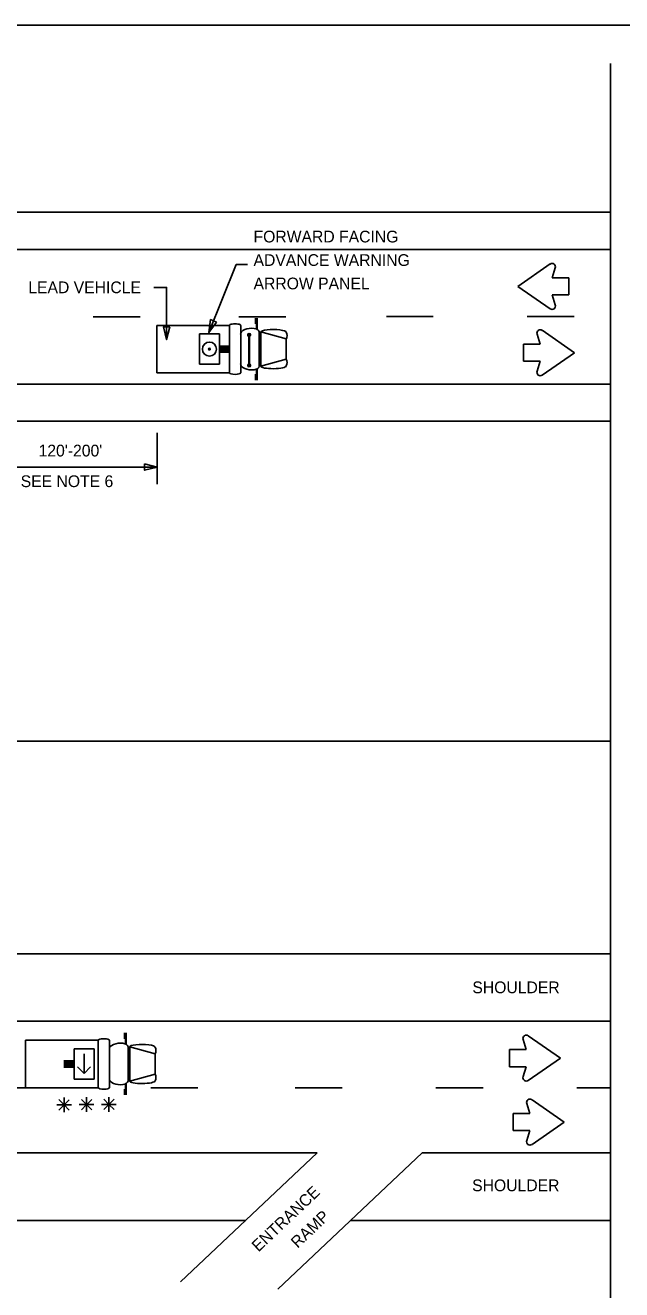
# Model space of a CAD drawing. Extents: x 1416408 to 1429341, y 372694 to 383211.
# Drawn here: x 1427162 to 1427672, y 373399 to 374480 of the extents above; entities that cross this region are included whole.
import ezdxf

# ---------------------------------------------------------------- set-up
doc = ezdxf.new("R2010")
doc.units = 0
for name, color, linetype in [('Default', 7, 'Continuous'), ('DSN_DRFT_Junk-No-Plot', 7, 'Continuous'), ('Working Level 1', 7, 'Continuous')]:
    doc.layers.add(name, color=color, linetype=linetype)

msp = doc.modelspace()

# ---------------------------------------------------------------- linework, layer by layer
at = {"layer": 'Default'}
for points in [[(1426234.9, 374479.9), (1426234.9, 372693.9), (1428995.1, 372693.9), (1428995.1, 374479.9)], [(1426234.9, 374479.9), (1426234.9, 372693.9), (1428995.1, 372693.9), (1428995.1, 374479.9)], [(1426234.9, 374479.9), (1428995.1, 374479.9), (1428995.1, 372693.9), (1426234.9, 372693.9)], [(1426234.9, 374479.9), (1426234.9, 372693.9), (1428995.1, 372693.9), (1428995.1, 374479.9)]]:
    msp.add_lwpolyline(points, close=True, dxfattribs=at)
at = {"layer": 'DSN_DRFT_Junk-No-Plot'}
msp.add_lwpolyline([(1426234.9, 374479.9), (1428995.1, 374479.9), (1428995.1, 372693.9), (1426234.9, 372693.9)], close=True, dxfattribs=at)
at = {"layer": 'Working Level 1'}
for p, q in [((1427662.6, 374447.3), (1427662.6, 372727.2)), ((1426338, 374320.2), (1427662.5, 374320.2)), ((1426338, 374288.1), (1427662.5, 374288.1)), ((1427583.2, 374256.6), (1427610.8, 374275.8)), ((1427612.6, 374263.9), (1427615.3, 374272.4)), ((1427583.2, 374256.6), (1427610.8, 374237.5)), ((1427626.9, 374263.9), (1427612.6, 374263.9)), ((1427626.9, 374263.9), (1427626.9, 374249.3)), ((1427626.9, 374249.3), (1427612.6, 374249.3)), ((1427612.6, 374249.3), (1427615.3, 374240.8)), ((1427359.1, 374224.6), (1427359.1, 374229.5)), ((1427359.9, 374219.8), (1427359.9, 374229.5)), ((1427360.5, 374219.8), (1427360.5, 374229.5)), ((1427274.5, 374223.3), (1427336.7, 374223.3)), ((1427274.5, 374182.7), (1427274.5, 374223.3)), ((1427274.5, 374223.3), (1427274.5, 374182.7)), ((1427311.1, 374216), (1427328.1, 374216)), ((1427311.1, 374216), (1427311.1, 374190)), ((1427328.1, 374190), (1427328.1, 374216)), ((1427336.7, 374203), (1427336.7, 374223.3)), ((1427346.3, 374203), (1427346.3, 374223.3)), ((1427352.3, 374215.4), (1427352.3, 374215.4)), ((1427353.4, 374214.8), (1427353.4, 374189.6)), ((1427353.4, 374214.8), (1427353.4, 374189.6)), ((1427353.5, 374214.8), (1427353.5, 374189.6)), ((1427353.6, 374214.8), (1427353.6, 374189.6)), ((1427353.8, 374216.2), (1427353.8, 374216.2)), ((1427353.8, 374214.8), (1427353.8, 374189.6)), ((1427362.2, 374203), (1427362.2, 374217.7)), ((1427363.5, 374217.7), (1427385.3, 374211.7)), ((1427363.5, 374203), (1427363.5, 374217.7)), ((1427602.4, 374207.2), (1427599.7, 374215.7)), ((1427631.7, 374199.9), (1427604.1, 374219.1)), ((1427328.1, 374205.6), (1427336.7, 374205.6)), ((1427328.1, 374204.3), (1427336.7, 374204.3)), ((1427328.1, 374203), (1427336.7, 374203)), ((1427336.7, 374203), (1427336.7, 374182.7)), ((1427346.3, 374203), (1427346.3, 374182.7)), ((1427362.2, 374203), (1427362.2, 374188.4)), ((1427363.5, 374203), (1427363.5, 374188.4)), ((1427385.3, 374203), (1427385.3, 374211.7)), ((1427385.3, 374203), (1427385.3, 374194.4)), ((1427588, 374192.6), (1427588, 374207.2)), ((1427588, 374207.2), (1427602.4, 374207.2)), ((1427328.1, 374201.7), (1427336.7, 374201.7)), ((1427328.1, 374200.4), (1427336.7, 374200.4)), ((1427363.5, 374188.4), (1427385.3, 374194.4)), ((1427588, 374192.6), (1427602.4, 374192.6)), ((1427602.4, 374192.6), (1427599.7, 374184.1)), ((1427631.7, 374199.9), (1427604.1, 374180.8)), ((1427274.5, 374182.7), (1427336.7, 374182.7)), ((1427311.1, 374190), (1427328.1, 374190)), ((1427352.4, 374189.4), (1427352.4, 374189.4)), ((1427353.9, 374190.2), (1427353.9, 374190.2)), ((1427359.1, 374181.5), (1427359.1, 374176.5)), ((1427359.9, 374186.3), (1427359.9, 374176.5)), ((1427360.5, 374186.3), (1427360.5, 374176.5)), ((1426338, 374173.1), (1427662.5, 374173.1)), ((1426338, 374141.5), (1427662.5, 374141.5)), ((1427274.8, 374131.4), (1427274.8, 374087.5)), ((1427136.9, 374102.1), (1427274.8, 374102.1)), ((1426338, 373867.7), (1427663, 373867.7)), ((1426338, 373686), (1427663, 373686)), ((1426819.9, 373628.3), (1427663, 373628.3)), ((1427246.9, 373613.2), (1427246.9, 373618.2)), ((1427247.7, 373608.5), (1427247.7, 373618.2)), ((1427248.3, 373608.5), (1427248.3, 373618.2)), ((1427162.4, 373612), (1427224.5, 373612)), ((1427162.4, 373571.4), (1427162.4, 373612)), ((1427162.4, 373612), (1427162.4, 373571.4)), ((1427224.5, 373591.7), (1427224.5, 373612)), ((1427234.1, 373591.7), (1427234.1, 373612)), ((1427590.5, 373604), (1427587.8, 373612.5)), ((1427619.8, 373596.7), (1427592.2, 373615.9)), ((1427220.9, 373604.7), (1427203.9, 373604.7)), ((1427203.9, 373578.7), (1427203.9, 373604.7)), ((1427212.4, 373600.3), (1427212.4, 373583.7)), ((1427220.9, 373604.7), (1427220.9, 373578.7)), ((1427250, 373591.7), (1427250, 373606.4)), ((1427251.4, 373606.4), (1427273.1, 373600.3)), ((1427251.4, 373591.7), (1427251.4, 373606.4)), ((1427273.1, 373591.7), (1427273.1, 373600.3)), ((1427576.1, 373589.4), (1427576.1, 373604)), ((1427576.1, 373604), (1427590.5, 373604)), ((1427619.8, 373596.7), (1427592.2, 373577.6)), ((1427203.9, 373594.3), (1427195.2, 373594.3)), ((1427203.9, 373593), (1427195.2, 373593)), ((1427203.9, 373591.7), (1427195.2, 373591.7)), ((1427203.9, 373590.4), (1427195.2, 373590.4)), ((1427203.9, 373589.1), (1427195.2, 373589.1)), ((1427212.4, 373583.7), (1427206.8, 373589.3)), ((1427212.4, 373583.7), (1427217.8, 373589.2)), ((1427224.5, 373591.7), (1427224.5, 373571.4)), ((1427234.1, 373591.7), (1427234.1, 373571.4)), ((1427250, 373591.7), (1427250, 373577.1)), ((1427251.4, 373591.7), (1427251.4, 373577.1)), ((1427273.1, 373591.7), (1427273.1, 373583.1)), ((1427576.1, 373589.4), (1427590.5, 373589.4)), ((1427590.5, 373589.4), (1427587.8, 373580.9)), ((1427220.9, 373578.7), (1427203.9, 373578.7)), ((1427247.7, 373575), (1427247.7, 373565.2)), ((1427248.3, 373575), (1427248.3, 373565.2)), ((1427251.4, 373577.1), (1427273.1, 373583.1)), ((1427162.4, 373571.4), (1427224.5, 373571.4)), ((1427246.9, 373570.2), (1427246.9, 373565.2)), ((1427633.8, 373571.4), (1427663, 373571.4)), ((1427195.3, 373556.7), (1427189.1, 373556.7)), ((1427195.3, 373556.7), (1427190.9, 373561.2)), ((1427195.3, 373556.7), (1427190.9, 373552.3)), ((1427195.2, 373556.6), (1427199.6, 373561.1)), ((1427195.3, 373556.7), (1427195.3, 373563)), ((1427195.3, 373556.7), (1427199.7, 373552.3)), ((1427195.3, 373556.7), (1427195.3, 373550.4)), ((1427195.3, 373556.7), (1427201.6, 373556.7)), ((1427214.6, 373557), (1427208.3, 373557)), ((1427214.6, 373557), (1427210.2, 373561.4)), ((1427214.6, 373557), (1427210.2, 373552.5)), ((1427214.5, 373556.9), (1427218.9, 373561.3)), ((1427214.6, 373557), (1427214.6, 373563.3)), ((1427214.6, 373557), (1427219, 373552.5)), ((1427214.6, 373557), (1427214.6, 373550.7)), ((1427214.6, 373557), (1427220.8, 373557)), ((1427233.7, 373557.1), (1427227.4, 373557.1)), ((1427233.7, 373557.1), (1427229.3, 373561.6)), ((1427233.7, 373557.1), (1427229.3, 373552.7)), ((1427233.6, 373557), (1427238, 373561.5)), ((1427233.7, 373557.1), (1427233.7, 373563.4)), ((1427233.7, 373557.1), (1427238.1, 373552.7)), ((1427233.7, 373557.1), (1427233.7, 373550.8)), ((1427233.7, 373557.1), (1427239.9, 373557.1)), ((1427593.6, 373549.3), (1427590.9, 373557.8)), ((1427623, 373542), (1427595.4, 373561.1)), ((1427579.3, 373534.7), (1427579.3, 373549.3)), ((1427579.3, 373549.3), (1427593.6, 373549.3)), ((1427579.3, 373534.7), (1427593.6, 373534.7)), ((1427593.6, 373534.7), (1427590.9, 373526.2)), ((1427623, 373542), (1427595.4, 373522.9)), ((1426338, 373515.7), (1427411.7, 373515.7)), ((1427411.7, 373515.7), (1427294.9, 373405.3)), ((1427501.4, 373515.7), (1427378, 373399.1)), ((1427501.4, 373515.7), (1427663, 373515.7)), ((1426338, 373458), (1427350.7, 373458)), ((1427440.3, 373458), (1427663, 373458))]:
    msp.add_line(p, q, dxfattribs=at)
for points in [[(1427319.1, 374217.1), (1427342.5, 374275.3), (1427352.1, 374275.3)], [(1427283, 374211.1), (1427283, 374255.8), (1427272, 374255.8)], [(1427220.3, 374230.5), (1427260.5, 374230.5)], [(1427344.7, 374230.5), (1427384.9, 374230.5)], [(1427470.9, 374231), (1427511, 374231)], [(1427591.4, 374231), (1427631.5, 374231)], [(1427352.3, 374215.4), (1427353.1, 374214)], [(1427352.3, 374214.9), (1427352.7, 374214.2)], [(1427352.4, 374215.7), (1427353.4, 374213.9)], [(1427352.6, 374215.9), (1427353.7, 374213.9)], [(1427352.8, 374216.1), (1427354, 374214)], [(1427353, 374216.2), (1427354.2, 374214.1)], [(1427353.2, 374216.3), (1427354.3, 374214.3)], [(1427353.4, 374216.3), (1427354.5, 374214.5)], [(1427353.8, 374216.3), (1427354.6, 374214.8)], [(1427354.1, 374216.2), (1427354.7, 374215.2)], [(1427352.4, 374189.4), (1427353.2, 374188)], [(1427352.4, 374188.9), (1427352.8, 374188.2)], [(1427352.5, 374189.7), (1427353.5, 374187.9)], [(1427352.7, 374189.9), (1427353.8, 374187.9)], [(1427352.8, 374190.1), (1427354, 374188)], [(1427353, 374190.2), (1427354.2, 374188.1)], [(1427353.3, 374190.3), (1427354.4, 374188.3)], [(1427353.5, 374190.3), (1427354.6, 374188.5)], [(1427353.8, 374190.3), (1427354.7, 374188.8)], [(1427354.2, 374190.2), (1427354.8, 374189.1)], [(1427146.8, 373571.4), (1427187, 373571.4)], [(1427269.5, 373571.4), (1427309.7, 373571.4)], [(1427392.8, 373571.4), (1427433, 373571.4)], [(1427513.3, 373571.4), (1427553.5, 373571.4)]]:
    msp.add_lwpolyline(points, dxfattribs=at)
for points in [[(1427325.6, 374226.1), (1427319.1, 374217.1), (1427320.6, 374228.2)], [(1427285.6, 374222), (1427283, 374211.1), (1427280.3, 374222)], [(1427264.1, 374104.8), (1427274.8, 374102.1), (1427264.1, 374099.4)]]:
    msp.add_lwpolyline(points, close=True, dxfattribs=at)
for centre, major_axis, ratio, start_param, end_param in [((1427612.5, 374273.3), (0, -2.96), 0.989089, 1.259821, 3.74278), ((1427612.5, 374239.9), (0, -2.96), 0.989089, 5.681999, 8.164958), ((1427341.5, 374223.3), (4.76, 0), 0.27289, 6.283185, 9.424778), ((1427354.2, 374216.7), (7.98, 1.01), 0.50847, 6.28135, 9.422943), ((1427374.4, 374217.5), (10.9, -0.1), 0.205643, 0.000054, 3.141647), ((1427380, 374214.5), (0, 6.1), 0.989089, 4.221603, 5.203174), ((1427602.5, 374216.6), (0, 2.96), 0.989089, 5.681999, 8.164958), ((1427380, 374191.5), (0, 6.1), 0.989089, 4.221604, 5.203174), ((1427341.5, 374182.7), (4.76, 0), 0.27289, 3.141593, 6.283185), ((1427354.2, 374189.4), (7.98, -1.01), 0.50847, 3.143427, 6.28502), ((1427374.4, 374188.5), (10.9, 0.1), 0.205643, 3.141539, 6.283131), ((1427602.5, 374183.2), (0, 2.96), 0.989089, 1.259821, 3.74278), ((1427229.3, 373612), (4.76, 0), 0.27289, 6.283185, 9.424778), ((1427242, 373605.4), (7.98, 1.01), 0.50847, 6.28135, 9.422943), ((1427262.2, 373606.2), (10.9, -0.1), 0.205643, 0.000054, 3.141647), ((1427590.6, 373613.4), (0, 2.96), 0.989089, 5.681999, 8.164958), ((1427267.8, 373603.2), (0, 6.1), 0.989089, 4.221603, 5.203174), ((1427242, 373578.1), (7.98, -1.01), 0.50847, 3.143427, 6.28502), ((1427262.2, 373577.2), (10.9, 0.1), 0.205643, 3.141539, 6.283131), ((1427267.8, 373580.2), (0, 6.1), 0.989089, 4.221604, 5.203174), ((1427590.6, 373580), (0, 2.96), 0.989089, 1.259821, 3.74278), ((1427229.3, 373571.4), (4.76, 0), 0.27289, 3.141593, 6.283185), ((1427593.7, 373558.7), (0, 2.96), 0.989089, 5.681999, 8.164958), ((1427593.7, 373525.3), (0, 2.96), 0.989089, 1.259821, 3.74278)]:
    msp.add_ellipse(centre, major_axis=major_axis, ratio=ratio, start_param=start_param, end_param=end_param, dxfattribs=at)
for centre, major_axis in [((1427353.5, 374215.1), (0, -1.22)), ((1427319.6, 374203), (0, -6.07)), ((1427319.6, 374203), (0, 0.755)), ((1427353.6, 374189.1), (0, -1.22))]:
    msp.add_ellipse(centre, major_axis=major_axis, ratio=0.989089, dxfattribs=at)

# ---------------------------------------------------------------- texts
for s, height, p in [('FORWARD FACING', 10.046, (1427357.3, 374294.2)), ('ADVANCE WARNING ', 10.046, (1427357.3, 374274.1)), ('LEAD VEHICLE', 10.046, (1427164.7, 374250.8)), ('ARROW PANEL', 10.046, (1427357.3, 374254.1)), ("120'-200'", 10.05, (1427173.5, 374111.2)), ('SEE NOTE 6', 10.05, (1427158.2, 374085))]:
    msp.add_text(s, height=height, dxfattribs=at).set_placement(p)
for s, height, rotation, p in [('SHOULDER', 10.05, 0, (1427544.4, 373652.2)), ('SHOULDER', 10.05, 0, (1427544.2, 373482.9)), ('ENTRANCE', 10, 43.3928, (1427361.5, 373430.5)), ('RAMP', 10, 43.3928, (1427395, 373433.6))]:
    msp.add_text(s, height=height, rotation=rotation, dxfattribs=at).set_placement(p)

doc.saveas('drawing.dxf')
